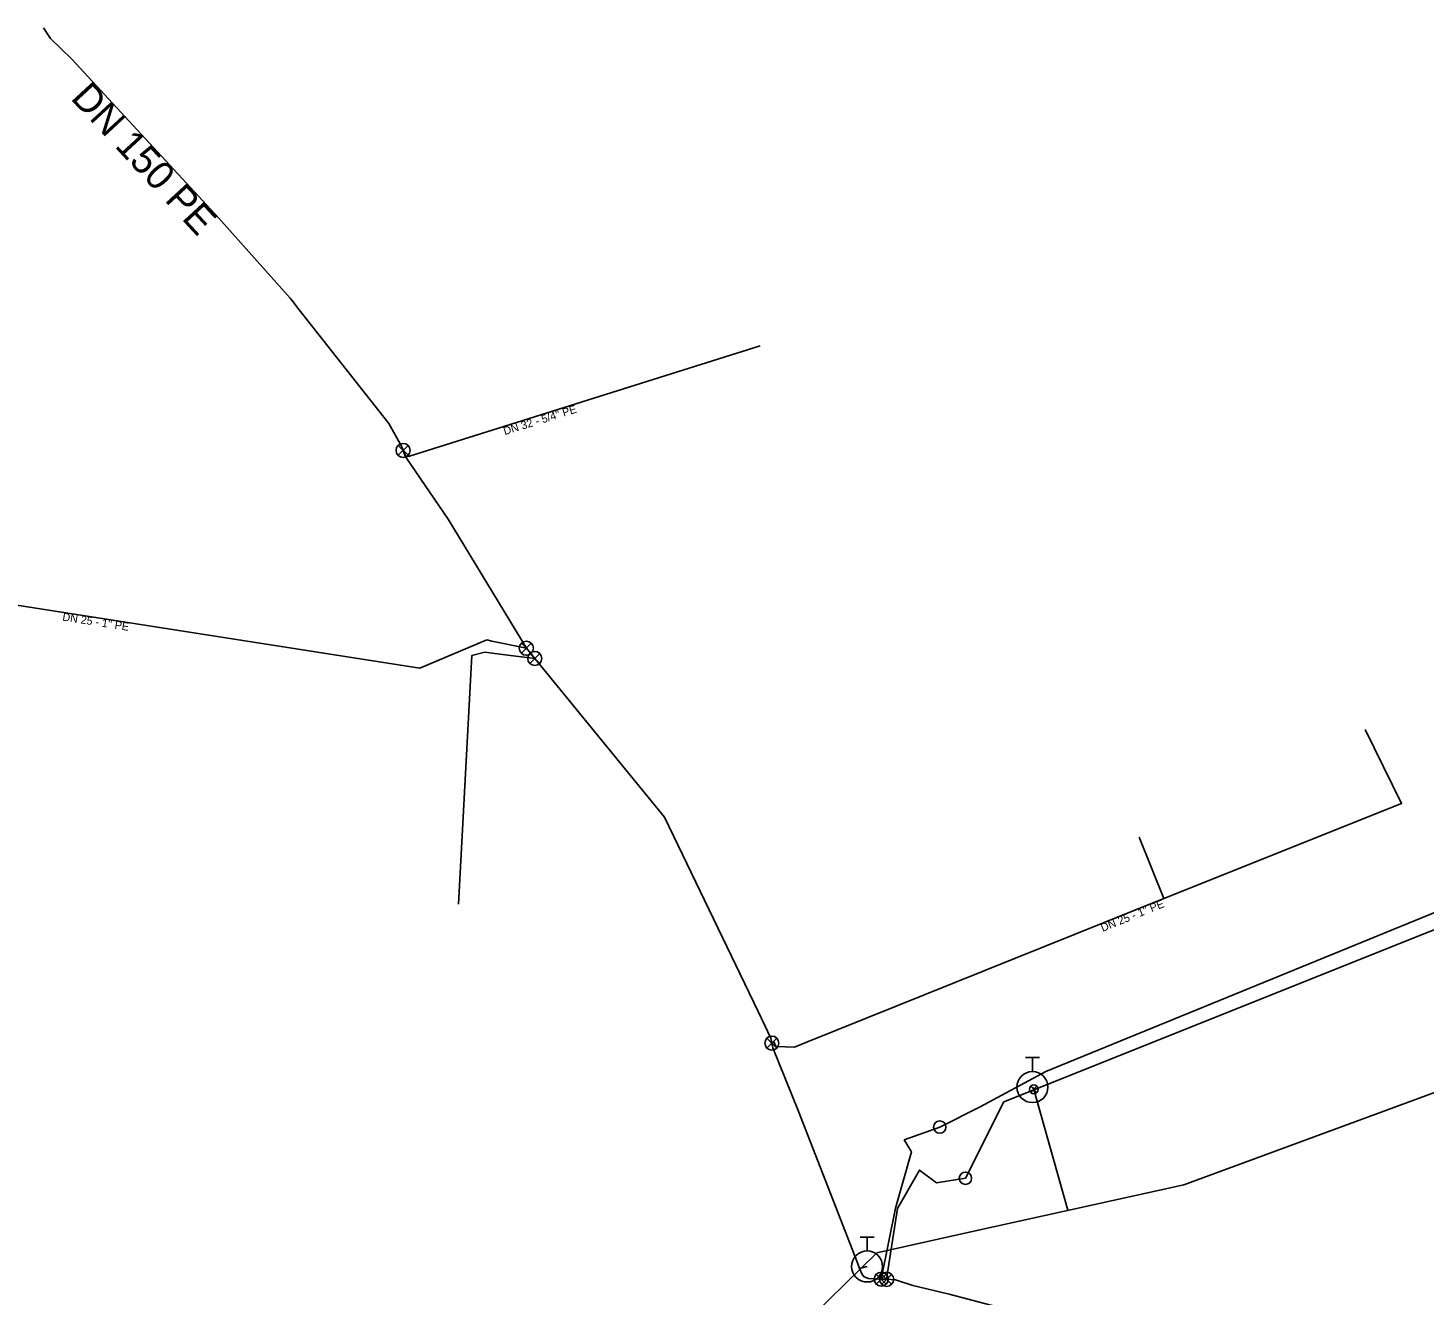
# Model space of a CAD drawing. Extents: x -451355 to -449353, y -1101368 to -1101089.
# Drawn here: x -449481.2 to -449401.8, y -1101295.1 to -1101223 of the extents above; entities that cross this region are included whole.
import ezdxf

# ---------------------------------------------------------------- set-up
doc = ezdxf.new("R2010")
doc.units = 0
for name, color, linetype in [('_hydrantova_odbocka_', 7, 'Continuous'), ('_pripojka_prevzato_z_dokumentace_', 7, 'Continuous'), ('_pripojka_priblizne_', 7, 'Continuous'), ('_voda_smvak_prevzato_z_dokumentace_', 7, 'Continuous'), ('Default', 7, 'Continuous'), ('MoLevel 27', 7, 'Continuous'), ('MoLevel 28', 7, 'Continuous'), ('MoLevel 30', 7, 'Continuous'), ('MoLevel 46', 7, 'Continuous'), ('MoLevel 53', 7, 'Continuous'), ('MoLevel 55', 7, 'Continuous')]:
    doc.layers.add(name, color=color, linetype=linetype)

# ---------------------------------------------------------------- blocks, each defined once
blk = doc.blocks.new('_uzaver_')
at = {"layer": 'Default'}
for p, q in [((-0.000035, -0.000035), (0.000035, 0.000035)), ((0.000035, -0.000035), (-0.000035, 0.000035))]:
    blk.add_line(p, q, dxfattribs=at)
for radius in [0.00005, 0.0000025]:
    blk.add_circle((0, 0), radius, dxfattribs=at)
blk = doc.blocks.new('_uzaver_pripojka_')
at = {"layer": 'Default'}
for p, q in [((-0.000035, -0.000035), (0.000035, 0.000035)), ((0.000035, -0.000035), (-0.000035, 0.000035))]:
    blk.add_line(p, q, dxfattribs=at)
for radius in [0.00005, 0.0000025]:
    blk.add_circle((0, 0), radius, dxfattribs=at)
blk = doc.blocks.new('_hydrant_voda_')
at = {"layer": 'Default'}
for p, q in [((-0.0000225, 0.000095), (0.0000225, 0.000095)), ((0, 0.000095), (0, 0.00005))]:
    blk.add_line(p, q, dxfattribs=at)
blk.add_circle((0, 0), 0.00005, dxfattribs=at)
blk = doc.blocks.new('_sachta_voda_')
at = {"layer": 'Default'}
blk.add_circle((0, 0), 0.000035, dxfattribs=at)

msp = doc.modelspace()

# ---------------------------------------------------------------- linework, layer by layer
at = {"layer": '_hydrantova_odbocka_'}
msp.add_line((-449433.95, -1101293.57), (-449433.52, -1101293.46), dxfattribs=at)
msp.add_lwpolyline([(-449422.103, -1101290.267), (-449424.04, -1101283.39), (-449424.12, -1101283.26)], dxfattribs=at)
at = {"layer": '_pripojka_prevzato_z_dokumentace_'}
for p, q in [((-449459.54, -1101247.38), (-449439.61, -1101241.12)), ((-449455.14, -1101257.84), (-449454.857, -1101257.899)), ((-449454.857, -1101257.899), (-449452.9, -1101258.31)), ((-449454.405, -1101258.646), (-449455.26, -1101258.54)), ((-449452.424, -1101258.892), (-449454.405, -1101258.646)), ((-449416.64, -1101272.54), (-449418.05, -1101269.05)), ((-449416.64, -1101272.54), (-449435.266, -1101280.02)), ((-449435.266, -1101280.02), (-449437.01, -1101280.72))]:
    msp.add_line(p, q, dxfattribs=at)
for points in [[(-449459.906, -1101247.062), (-449459.78, -1101247.45), (-449459.66, -1101247.38), (-449459.54, -1101247.38)], [(-449455.14, -1101257.84), (-449458.96, -1101259.45), (-449482.13, -1101255.83)], [(-449405.2, -1101262.93), (-449403.13, -1101267.14), (-449416.64, -1101272.54)], [(-449438.941, -1101280.764), (-449438.82, -1101280.68), (-449438.72, -1101280.95), (-449437.66, -1101280.99), (-449437.01, -1101280.72)], [(-449432.72, -1101294.18), (-449431.9, -1101290.15), (-449431, -1101286.95), (-449431.41, -1101286.25)], [(-449432.41, -1101294.19), (-449431.79, -1101290.17), (-449430.54, -1101287.98), (-449429.58, -1101288.71)]]:
    msp.add_lwpolyline(points, dxfattribs=at)
at = {"layer": '_pripojka_priblizne_'}
for p, q in [((-449431.41, -1101286.25), (-449429.394, -1101285.53)), ((-449429.58, -1101288.71), (-449427.928, -1101288.447))]:
    msp.add_line(p, q, dxfattribs=at)
for points in [[(-449429.394, -1101285.53), (-449427.083, -1101284.38), (-449423.353, -1101282.377), (-449387.371, -1101267.661), (-449353.079, -1101254.309)], [(-449427.928, -1101288.447), (-449425.746, -1101284.099), (-449353.079, -1101255.052)], [(-449455.26, -1101258.54), (-449455.997, -1101258.721), (-449456.755, -1101272.854)]]:
    msp.add_lwpolyline(points, dxfattribs=at)
at = {"layer": '_voda_smvak_prevzato_z_dokumentace_'}
for points in [[(-449425.48, -1101295.93), (-449428.85, -1101295.03), (-449430.92, -1101294.55), (-449431.91, -1101294.21), (-449432.41, -1101294.19), (-449432.72, -1101294.18), (-449433.45, -1101294.15), (-449433.69, -1101294.05), (-449433.81, -1101293.91), (-449433.95, -1101293.57), (-449434.07, -1101293.25), (-449437.44, -1101284.59), (-449438.89, -1101281.02), (-449438.941, -1101280.764), (-449439, -1101280.47), (-449439.72, -1101278.96), (-449445.04, -1101267.91), (-449452.424, -1101258.892), (-449452.9, -1101258.31), (-449457.35, -1101250.97), (-449459.72, -1101247.51), (-449459.906, -1101247.062), (-449459.99, -1101246.86), (-449460.72, -1101245.54), (-449465.82, -1101239.07), (-449466.242, -1101238.524), (-449466.33, -1101238.41), (-449470.39, -1101233.86), (-449478.75, -1101224.82), (-449479.96, -1101223.64), (-449480.142, -1101223.368), (-449480.358, -1101223.042)], [(-449353.079, -1101265.823), (-449415.519, -1101288.813), (-449427.624, -1101291.487), (-449432.961, -1101292.675), (-449446.62, -1101306.05), (-449564.49, -1101281.4)]]:
    msp.add_lwpolyline(points, dxfattribs=at)

# ---------------------------------------------------------------- block references
at = {"layer": 'MoLevel 27', "xscale": 5000, "yscale": 5000}
msp.add_blockref('_uzaver_', (-449424.04, -1101283.39), dxfattribs=at)
at = {"layer": 'MoLevel 28', "xscale": 17636.68430335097, "yscale": 17636.68430335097}
for p in [(-449424.12, -1101283.26), (-449433.52, -1101293.46)]:
    msp.add_blockref('_hydrant_voda_', p, dxfattribs=at)
at = {"layer": 'MoLevel 30', "xscale": 10000, "yscale": 10000}
msp.add_blockref('_sachta_voda_', (-449429.394, -1101285.53), dxfattribs=at)
at = {"layer": 'MoLevel 30', "xscale": 10000.000000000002, "yscale": 9999.999999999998, "rotation": -53.15323550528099}
msp.add_blockref('_sachta_voda_', (-449427.928, -1101288.447), dxfattribs=at)
at = {"layer": 'MoLevel 53', "xscale": 7999.999999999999, "yscale": 7999.999999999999}
for p in [(-449459.91, -1101247.06), (-449452.9, -1101258.31), (-449452.42, -1101258.89), (-449438.94, -1101280.76), (-449432.72, -1101294.18), (-449432.41, -1101294.19)]:
    msp.add_blockref('_uzaver_pripojka_', p, dxfattribs=at)

# ---------------------------------------------------------------- texts
at = {"layer": 'MoLevel 46'}
msp.add_text('DN 150 PE', height=1.6049, rotation=312.762, dxfattribs=at).set_placement((-449478.861, -1101227.063))
at = {"layer": 'MoLevel 55'}
for s, rotation, p in [("DN 32 - 5/4'' PE", 17.43747, (-449454.123, -1101246.198)), ("DN 25 - 1'' PE", 351.1201, (-449479.304, -1101256.732)), ("DN 25 - 1'' PE", 21.87896, (-449420.127, -1101274.436))]:
    msp.add_text(s, height=0.455, rotation=rotation, dxfattribs=at).set_placement(p)

doc.saveas('drawing.dxf')
